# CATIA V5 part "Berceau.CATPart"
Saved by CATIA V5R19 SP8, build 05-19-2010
Part number: Berceau
Publications: "point_axe_pivot_canon_berceau"
Bounding box of the stored display mesh (mm): x -975 to 975, y -1050 to 800, z -150 to 197.999
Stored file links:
  G:\EU_thinkMotion\CFAO_2010\MMS_groupe2\MMS_groupe2\OK\mmartini\mmartiniCFAO\Berceau.CATPart
  C:\Users\Mathieu Martini\Desktop\CFAO\Animation\CFAO.CATProduct
  G:\EU_thinkMotion\CFAO_2010\MMS_groupe2\MMS_groupe2\OK\mmartini\mmartiniCFAO\Squelette.CATPart
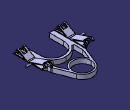
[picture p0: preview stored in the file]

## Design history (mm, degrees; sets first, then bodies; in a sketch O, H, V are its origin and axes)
Parameters
  diametre_canon = 150 mm
External parameters (linked from other documents)
  External.diametre_canon = 150 mm
  External.diametre_verin = 120 mm
AxisSystem1: origin (0, 0, 0), X (1, 0, 0), Y (0, 1, 0), Z (0, 0, 1)
Set1
  Sketch1 on Plane1, origin (0, 0, 0), H (1, 0, 0), V (0, 1, 0)
    circle A1 centre (0, 450) radius 300
    point P1 (0, 450)
    reference projected point E1 (0, 450) from Point2
    arc A2 centre (0, 450) radius 350 from (325.3452, 579.0368) to (-325.3452, 579.0368) ccw
    reference intersected line E2 through (0, 900) direction (-1, 0) from Plane2
    line L1 (555, 0) -> (325.3452, 579.0368)
    point P2 (325.3452, 579.0368)
    point P3 (555, 0)
    reference projected line E3 through (0, 0) direction (1, 0) from Line1
    reference projected point E4 (675, 0) from Point3
    line L2 (555, 0) -> (555, -570)
    point P4 (555, 0)
    point P5 (555, -570)
    reference projected line E5 through (0, -450) direction (1, 0) from Line2
    point P6 (555, -570)
    line L3 (555, -570) -> (405, -570)
    point P7 (405, -570)
    arc A3 centre (0, -570) radius 405 from (405, -570) to (-405, -570) ccw
    point P8 (0, -570)
    reference projected line E6 through (0, 0) direction (0, 1) from Line3
    axis line L4 (0, 455.2396) -> (0, -570)
    point P9 (0, 455.2396)
    point P10 (-555, -570)
    point P11 (-555, 0)
    line L5 (-555, 0) -> (-555, -570)
    point P12 (-405, -570)
    line L6 (-555, -570) -> (-405, -570)
    point P13 (-325.3452, 579.0368)
    point P14 (-555, 0)
    line L7 (-555, 0) -> (-325.3452, 579.0368)
    line L8 (335.4492, 350.131) -> (474.3165, 0)
    point P15 (335.4492, 350.131)
    point P16 (474.3165, 0)
    reference projected line E7 through (0, 0) direction (1, 0) from Line1
    line L9 (474.3165, 0) -> (474.3165, -303.6424)
    line L10 (474.3165, -303.6424) -> (399.3165, -303.6424)
    point P17 (474.3165, -303.6424)
    point P18 (399.3165, -303.6424)
    arc A4 centre (0, -570) radius 480 from (399.3165, -303.6424) to (0, -90) ccw
    point P19 (0, -90)
    point P20 (-474.3165, 0)
    point P21 (-335.4492, 350.131)
    line L11 (-335.4492, 350.131) -> (-474.3165, 0)
    point P22 (-474.3165, -303.6424)
    line L12 (-474.3165, 0) -> (-474.3165, -303.6424)
    point P23 (-399.3165, -303.6424)
    line L13 (-474.3165, -303.6424) -> (-399.3165, -303.6424)
    point P24 (0, -90)
    arc A5 centre (0, -570) radius 480 from (-399.3165, -303.6424) to (0, -90) cw
    arc A6 centre (0, 450) radius 350 from (-335.4492, 350.131) to (335.4492, 350.131) ccw
    radius A1 = 300 {= External.diametre_canon *2}
    distance A2 E2 = 100 {= External.diametre_canon /1.5}
    distance E4 P3 = 120 {= External.diametre_verin}
    distance P5 E5 = 120 {= External.diametre_verin}
    distance P8 L3 = 0
    length L3 = 150 {= External.diametre_canon}
    distance L8 L1 = 75 {= External.diametre_canon /2}
    length L10 = 75 {= External.diametre_canon /2}
    distance A4 A3 = 75 {= External.diametre_canon /2}
    coincidence: P1 E1, P3 E3, P4 H, P6 P5, P8 E6, P9 V, P4 P3, P16 E7, L4 P19, A2 A6, P11 P14, P19 P24
    tangency: L1 A2
    vertical: L2 V, L4 V
    horizontal: L3 H, L10 H
    symmetry: P5 P10 L4, P4 P11 L4, L2 L5 L4, P7 P12 L4, L3 L6 L4, P2 P13 L4, P3 P14 L4, L1 L7 L4, P16 P20 L4, P15 P21 L4, L8 L11 L4, P17 P22 L4, L9 L12 L4, P18 P23 L4, L10 L13 L4, P19 P24 L4, A4 A5 L4
    parallelism: L9 L2
  Point1 "point_axe_pivot_canon_berceau": (0, 450 {= diametre_canon *3}, 0)
Set2
  Plane1: linked copy from another document
  Point2 "point_axe_pivot_canon_berceau": linked copy from another document
  Plane2 "Plan_berceaumax": linked copy from another document
  Line1 "Droite_plan_de_construction_verin": linked copy from another document
  Point3 "Point_verin_droit": linked copy from another document
  Line2 "axe_berceau_jambe_roue": linked copy from another document
  Line3 "axe_canon": linked copy from another document
  Point4 "pt_canonvertical": linked copy from another document
  Plane3 "Plan_rayon_int_verin_droit": linked copy from another document
  Plane4 "arret_berceau_droit": linked copy from another document
  Plane5 "arret_berceau_gauche": linked copy from another document
  Plane6 "arret_berceau_ext_droit": linked copy from another document
  Point5: linked copy from another document
  Plane7 "arret_berceau_ext_gauche": linked copy from another document
  Plane8 "Plan_verin_gauche": linked copy from another document
  Point6: linked copy from another document
  Plane9 "Plan_verin_droit": linked copy from another document
  Plane10: linked copy from another document
  Plane11 "Plan_rayon_ext_verin_droit": linked copy from another document
  Line4 "axe_berceau_jambe": linked copy from another document
  Plane12 "arret_berceau_droit": linked copy from another document
  Plane13 "Plan_rayon_ext_verin_gauche": linked copy from another document
Body1 (main body)
  Pad1: profile Sketch1, direction (0, 0, -1), length 150 {= External.diametre_canon}
  Sketch2 on face of Pad1 from Sketch1.L1, origin (479.563, 190.202, 515.9045), H (0.1359, -0.3427, -0.9296), V (-0.3427, 0.8641, -0.3687)
    circle A1 centre (0, 450) radius 300
    point P1 (0, 450)
    reference projected point E1 (325.3452, 579.0368) from Point2
    arc A2 centre (0, 450) radius 445.2859 from (434.875, 545.7247) to (-434.875, 545.7247) ccw
    reference intersected line E2 through (13.9508, 826.9849) direction (-0.9296, -0.3687) from Plane2
    line L1 (555, 0) -> (434.875, 545.7247)
    point P2 (434.875, 545.7247)
    point P3 (555, 0)
    reference projected line E3 through (486.2175, 715.9045) direction (0.3687, -0.9296) from Line1
    reference projected point E4 (757.2222, 32.6106) from Point3
    line L2 (555, 0) -> (555, -570)
    point P4 (555, 0)
    point P5 (555, -570)
    reference projected line E5 through (463.061, 231.809) direction (0.3687, -0.9296) from Line2
    point P6 (555, -570)
    line L3 (555, -570) -> (405, -570)
    point P7 (405, -570)
    arc A3 centre (0, -570) radius 405 from (405, -570) to (-405, -570) ccw
    point P8 (0, -570)
    reference projected line E6 through (365.9045, 69.9126) direction (-0.3687, 0.9296) from Line3
    axis line L4 (0, 455.2396) -> (0, -570)
    point P9 (0, 455.2396)
    point P10 (-555, -570)
    point P11 (-555, 0)
    line L5 (-555, 0) -> (-555, -570)
    point P12 (-405, -570)
    line L6 (-555, -570) -> (-405, -570)
    point P13 (-434.875, 545.7247)
    point P14 (-555, 0)
    line L7 (-555, 0) -> (-434.875, 545.7247)
    line L8 (414.7961, 288.0627) -> (114.0902, 1654.1622)
    point P15 (414.7961, 288.0627)
    point P16 (114.0902, 1654.1622)
    reference projected line E7 through (486.2175, 715.9045) direction (0.3687, -0.9296) from Line1
    line L9 (114.0902, 1654.1622) -> (114.0902, -91.5944)
    line L10 (114.0902, -91.5944) -> (39.0902, -91.5944)
    point P17 (114.0902, -91.5944)
    point P18 (39.0902, -91.5944)
    arc A4 centre (0, -570) radius 480 from (39.0902, -91.5944) to (0, -90) ccw
    point P19 (0, -90)
    point P20 (-114.0902, 1654.1622)
    point P21 (-414.7961, 288.0627)
    line L11 (-414.7961, 288.0627) -> (-114.0902, 1654.1622)
    point P22 (-114.0902, -91.5944)
    line L12 (-114.0902, 1654.1622) -> (-114.0902, -91.5944)
    point P23 (-39.0902, -91.5944)
    line L13 (-114.0902, -91.5944) -> (-39.0902, -91.5944)
    point P24 (0, -90)
    arc A5 centre (0, -570) radius 480 from (-39.0902, -91.5944) to (0, -90) cw
    arc A6 centre (0, 450) radius 445.2859 from (-414.7961, 288.0627) to (414.7961, 288.0627) ccw
    radius A1 = 300 {= External.diametre_canon *2}
    distance A2 E2 = 100 {= External.diametre_canon /1.5}
    distance E4 P3 = 120 {= External.diametre_verin}
    distance P5 E5 = 120 {= External.diametre_verin}
    distance P8 L3 = 0
    length L3 = 150 {= External.diametre_canon}
    distance L8 L1 = 75 {= External.diametre_canon /2}
    length L10 = 75 {= External.diametre_canon /2}
    distance A4 A3 = 75 {= External.diametre_canon /2}
    coincidence: P1 E1, P3 E3, P4 H, P6 P5, P8 E6, P9 V, P4 P3, P16 E7, L4 P19, A2 A6, P11 P14, P19 P24
    tangency: L1 A2
    vertical: L2 V, L4 V
    horizontal: L3 H, L10 H
    symmetry: P5 P10 L4, P4 P11 L4, L2 L5 L4, P7 P12 L4, L3 L6 L4, P2 P13 L4, P3 P14 L4, L1 L7 L4, P16 P20 L4, P15 P21 L4, L8 L11 L4, P17 P22 L4, L9 L12 L4, P18 P23 L4, L10 L13 L4, P19 P24 L4, A4 A5 L4
    parallelism: L9 L2
  Sketch3 on face of Pad1 from Sketch1.L2, origin (555, 0, 0), H (0, 1, 0), V (0, 0, 1)
    circle A1 centre (0, 150) radius 24
    point P1 (0, 150)
    reference projected point E1 (0, 150) from Point4
    arc A2 centre (0, 150) radius 48 from (-47.1832, 158.8175) to (9.4359, 102.9366) ccw
    point P2 (0, 150)
    line L1 (-15.9554, 195.2706) -> (-570, 0)
    point P4 (-570, 0)
    reference projected point E2 (-570, 0) from vertex [face of Pad1 from Sketch1.L2 | start face of Pad1 | face of Pad1 from Sketch1.L3]
    point P5 (0, 102)
    line L2 (45.476, 134.64) -> (0, 0)
    point P6 (45.476, 134.64)
    line L3 (0, 0) -> (-570, 0)
    point P7 (0, 0)
    line L4 (9.4359, 102.9366) -> (-17.2258, 24)
    line L5 (-17.2258, 24) -> (-429.7032, 24)
    line L6 (-429.7032, 24) -> (-47.1832, 158.8175)
    arc A3 centre (0, 150) radius 48 from (45.476, 134.64) to (-15.9554, 195.2706) ccw
    radius A1 = 24 {= External.diametre_verin /5}
    distance A1 A2 = 24 {= External.diametre_verin /5}
    distance L4 L2 = 24 {= External.diametre_verin /5}
    distance L5 L3 = 24 {= External.diametre_verin /5}
    distance L6 L1 = 24 {= External.diametre_verin /5}
    coincidence: P1 E1, P2 P1, P4 H, P4 E2, P5 A2, P5 V, P6 A2, P7 L2, P7 V, A2 A3, O P7
    tangency: L1 A2, L2 A2
    horizontal: L5 H, L3 H
  Pad2: profile Sketch3, direction (1, 0, 0), up to Plane4
  Sketch4 on face of Pad1 from Sketch1.L5, origin (-555, 0, 0), H (0, -1, 0), V (0, 0, 1)
    projected line E1 (15.9554, 195.2706) -> (570, 0) from edge [start face of Pad2 | face of Pad2 from Sketch3.L1]
    projected line E2 (570, 0) -> (0, 0) from edge [start face of Pad2 | start face of Pad1]
    projected line E3 (0, 0) -> (-45.476, 134.64) from edge [start face of Pad2 | face of Pad2 from Sketch3.L2]
    projected arc E4 centre (0, 150) radius 48 from (15.9554, 195.2706) to (-45.476, 134.64) ccw from edge [start face of Pad2 | face of Pad2 from Sketch3.A3]
    projected circle E5 centre (0, 150) radius 24 from edge [face of Pad2 from Sketch3.A1 | start face of Pad2]
    projected arc E6 centre (0, 150) radius 48 from (-9.4359, 102.9366) to (47.1832, 158.8175) ccw from edge [face of Pad2 from Sketch3.A2 | start face of Pad2]
    projected line E7 (17.2258, 24) -> (-9.4359, 102.9366) from edge [face of Pad2 from Sketch3.L4 | start face of Pad2]
    projected line E8 (429.7032, 24) -> (17.2258, 24) from edge [face of Pad2 from Sketch3.L5 | start face of Pad2]
    projected line E9 (47.1832, 158.8175) -> (429.7032, 24) from edge [face of Pad2 from Sketch3.L6 | start face of Pad2]
  Pad3: profile Sketch4, direction (-1, 0, 0), up to Plane5
  Sketch5 on Plane6, origin (750, 0, 0), H (0, 1, 0), V (0, 0, 1)
    projected arc E1 centre (0, 150) radius 48 from (45.476, 134.64) to (-15.9554, 195.2706) ccw from edge [face of Pad2 from Sketch3.A3 | end face of Pad2]
    projected line E2 (-15.9554, 195.2706) -> (-570, 0) from edge [face of Pad2 from Sketch3.L1 | end face of Pad2]
    projected circle E3 centre (0, 150) radius 24 from edge [end face of Pad2 | face of Pad2 from Sketch3.A1]
    projected line E4 (-429.7032, 24) -> (-47.1832, 158.8175) from edge [face of Pad2 from Sketch3.L6 | end face of Pad2]
    point P6 (-47.1832, 158.8175)
    projected arc E5 centre (0, 150) radius 48 from (-47.1832, 158.8175) to (9.4359, 102.9366) ccw from edge [face of Pad2 from Sketch3.A2 | end face of Pad2]
    projected arc E6 centre (0, 150) radius 48 from (-47.1832, 158.8175) to (-21.9349, 107.305) ccw from edge [face of Pad2 from Sketch3.A2 | end face of Pad2]
    point P7 (-47.1832, 158.8175)
    point P8 (9.4359, 102.9366)
    line L1 (45.476, 134.64) -> (-107.5816, 0)
    point P9 (-107.5816, 0)
    line L2 (-107.5816, 0) -> (-570, 0)
    point P10 (-107.5816, 0)
    line L3 (-429.7032, 24) -> (-116.6354, 24)
    line L4 (-116.6354, 24) -> (-21.9349, 107.305)
    point P12 (-21.9349, 107.305)
    distance L4 L1 = 24 {= External.diametre_verin /5}
    coincidence: L1 P8, P9 H, P10 H, P12 E5, P6 P7, P9 P10
    horizontal: L2 H, L3 H
  Pad4: profile Sketch5, direction (1, 0, 0), length 50 {= External.diametre_canon /3}
  Sketch6 on end face of Pad2, origin (600, 0, 0), H (0, 1, 0), V (0, 0, 1)
    projected line E1 (-15.9554, 195.2706) -> (-570, 0) from edge [face of Pad4 from Sketch5.E2 | end face of Pad4]
    projected line E2 (-107.5816, 162.9773) -> (-570, 0) from edge [face of Pad4 from Sketch5.E2 | end face of Pad4]
    point P2 (-570, 0)
    projected line E3 (-570, 0) -> (-107.5816, 0) from edge [face of Pad4 from Sketch5.L2 | end face of Pad4]
    point P3 (-570, 0)
    point P4 (-107.5816, 0)
    projected line E4 (-47.1832, 158.8175) -> (-429.7032, 24) from edge [end face of Pad4 | face of Pad4 from Sketch5.E4]
    projected line E5 (-107.5816, 137.5303) -> (-429.7032, 24) from edge [end face of Pad4 | face of Pad4 from Sketch5.E4]
    point P7 (-429.7032, 24)
    projected line E6 (-116.6354, 24) -> (-21.9349, 107.305) from edge [end face of Pad4 | face of Pad4 from Sketch5.L4]
    projected line E7 (-429.7032, 24) -> (-116.6354, 24) from edge [end face of Pad4 | face of Pad4 from Sketch5.L3]
    point P10 (-429.7032, 24)
    axis line L1 (-107.5816, -5.232) -> (-107.5816, 242.1501)
    line L2 (-107.5816, 162.9773) -> (-107.5816, 137.5303)
    point P13 (-107.5816, 162.9773)
    point P14 (-107.5816, 137.5303)
    point P15 (-107.5816, 162.9773)
    point P16 (-107.5816, 137.5303)
    line L3 (-107.5816, 0) -> (-116.6354, 24)
    distance P4 L2 = 0
    vertical: L1 V, L2 V
    coincidence: P13 E1, P13 L1, P14 E4, L1 P15, L1 P16, P2 P3, P7 P10, P13 P15, P14 P16
  Pad5: profile Sketch6, direction (1, 0, 0), up to start face of Pad4
  Sketch7 on face of Pad2, origin (0, 0, 0), H (1, 0, 0), V (0, -1, 0)
  Sketch8 on face of Pad1 from Sketch1.L3, origin (0, -570, 0), H (1, 0, 0), V (0, 0, 1)
    projected line E1 (800, 0) -> (555, 0) from edge of Sketch7
    projected line E2 (555, 0) -> (555, -150) from edge [face of Pad1 from Sketch1.L3 | face of Pad1 from Sketch1.L2]
    line L1 (800, 0) -> (555, -150)
  SolidCombine1: FirstComponentProfile Sketch7, FirstComponentDirection Sketch7, SecondComponentProfile Sketch8, SecondComponentDirection Sketch8
  Sketch9 on Plane7, origin (-750, 0, 0), H (0, 1, 0), V (0, 0, 1)
    projected arc E1 centre (0, 150) radius 48 from (45.476, 134.64) to (-15.9554, 195.2706) ccw from edge [face of Pad4 from Sketch5.E1 | end face of Pad4]
    projected line E2 (-15.9554, 195.2706) -> (-570, 0) from edge [face of Pad2 | end face of Pad4]
    projected line E3 (-107.5816, 0) -> (-570, 0) from edge [end face of Pad4 | face of SolidCombine1 from Sketch8.L1]
    projected line E4 (-107.5816, 0) -> (45.476, 134.64) from edge [face of Pad4 from Sketch5.L1 | end face of Pad4]
    projected circle E5 centre (0, 150) radius 24 from edge [end face of Pad4 | face of Pad4 from Sketch5.E3]
    projected line E6 (-47.1832, 158.8175) -> (-429.7032, 24) from edge [end face of Pad4 | face of Pad2]
    projected arc E7 centre (0, 150) radius 48 from (-47.1832, 158.8175) to (-21.9349, 107.305) ccw from edge [end face of Pad4 | face of Pad4 from Sketch5.E6]
    projected line E8 (-116.6354, 24) -> (-21.9349, 107.305) from edge [end face of Pad4 | face of Pad4 from Sketch5.L4]
    projected line E9 (-429.7032, 24) -> (-116.6354, 24) from edge [end face of Pad4 | face of Pad2]
  Pad6: profile Sketch9, direction (1, 0, 0), length -50 {= -External.diametre_canon /3}
  Sketch10 on end face of Pad3, origin (-600, 0, 0), H (0, -1, 0), V (0, 0, 1)
    projected line E1 (15.9554, 195.2706) -> (570, 0) from edge [end face of Pad6 | face of Pad6 from Sketch9.E2]
    projected line E2 (107.5816, 162.9773) -> (570, 0) from edge [end face of Pad6 | face of Pad6 from Sketch9.E2]
    projected line E3 (570, 0) -> (107.5816, 0) from edge [end face of Pad6 | face of Pad6 from Sketch9.E3]
    point P4 (107.5816, 0)
    projected line E4 (429.7032, 24) -> (116.6354, 24) from edge [face of Pad6 from Sketch9.E9 | end face of Pad6]
    projected line E5 (47.1832, 158.8175) -> (429.7032, 24) from edge [face of Pad6 from Sketch9.E6 | end face of Pad6]
    projected line E6 (107.5816, 137.5303) -> (429.7032, 24) from edge [face of Pad6 from Sketch9.E6 | end face of Pad6]
    line L1 (116.6354, 24) -> (107.5816, 0)
    point P9 (116.6354, 24)
    point P10 (107.5816, 0)
    line L2 (107.5816, 137.5303) -> (107.5816, 162.9773)
    point P11 (107.5816, 137.5303)
    point P12 (107.5816, 162.9773)
    distance L2 P4 = 0
    angle L2 L1 = 159.3315
    coincidence: P9 E4, P10 H, L1 P4, P11 E5, P12 E1, P4 P10
    vertical: L2 V
  Pad7: profile Sketch10, direction (-1, 0, 0), up to start face of Pad6
  Sketch11 on face of Pad3, origin (0, 0, 0), H (1, 0, 0), V (0, -1, 0)
  Sketch12 on face of Pad1 from Sketch1.L6, origin (0, -570, 0), H (1, 0, 0), V (0, 0, 1)
    projected line E1 (-555, 0) -> (-800, 0) from edge of Sketch11
    projected line E2 (-555, 0) -> (-555, -150) from edge [face of Pad1 from Sketch1.L5 | face of Pad1 from Sketch1.L6]
    line L1 (-555, -150) -> (-800, 0)
  SolidCombine2: FirstComponentProfile Sketch11, FirstComponentDirection Sketch11, SecondComponentProfile Sketch12, SecondComponentDirection Sketch12
  Sketch13 on Plane8, origin (-675, 0, 0), H (0, 1, 0), V (0, 0, 1)
    projected line E1 (-570, -150) -> (-570, 0) from edge of Sketch14
    point P1 (-570, -150)
    line L1 (-570, 0) -> (-1050, 0)
    line L2 (-1050, 0) -> (-1050, -150)
    line L3 (-570, -150) -> (-1050, -150)
    point P5 (-570, -150)
    reference projected point E2 (-900, 150) from Point6
    distance L2 E2 = 150 {= External.diametre_canon}
    horizontal: L1 H, L3 H
    vertical: L2 V
    coincidence: P5 E1, P5 P1
  Sketch14 on face of Pad1, origin (0, -570, 0), H (1, 0, 0), V (0, 0, 1)
  SolidCombine3: FirstComponentProfile Sketch13, FirstComponentDirection Sketch13, SecondComponentProfile Sketch14, SecondComponentDirection Sketch14
  Sketch15 on Plane8, origin (-675, 0, 0), H (0, 1, 0), V (0, 0, 1)
    projected point E1 (-1050, 0) from edge of Sketch16
    point P1 (-1050, 0)
    line L1 (-1050, 0) -> (-933.1102, 172.4436)
    point P3 (-900, 150)
    reference projected point E2 (-900, 150) from Point6
    arc A1 centre (-900, 150) radius 40 from (-879.5307, 184.3658) to (-933.1102, 172.4436) ccw
    line L2 (-570, 0) -> (-879.5307, 184.3658)
    line L3 (-1050, 0) -> (-570, 0)
    radius A1 = 40 {= External.diametre_verin /3}
    coincidence: P1 E1, P3 E2
    tangency: L2 A1, L1 A1
    horizontal: L3 H
  Sketch16 on face of SolidCombine3, origin (0, 0, 0), H (1, 0, 0), V (0, 1, 0)
  SolidCombine4: FirstComponentProfile Sketch15, FirstComponentDirection Sketch15, SecondComponentProfile Sketch16, SecondComponentDirection Sketch16
  Sketch17 on face of Pad1, origin (0, -570, 0), H (1, 0, 0), V (0, 0, 1)
  Sketch18 on Plane9, origin (675, 0, 0), H (0, 1, 0), V (0, 0, 1)
  SolidCombine5: FirstComponentProfile Sketch17, FirstComponentDirection Sketch17, SecondComponentProfile Sketch18, SecondComponentDirection Sketch18
  Sketch19 on Plane9, origin (675, 0, 0), H (0, 1, 0), V (0, 0, 1)
  Sketch20 on face of Pad1, origin (0, 0, 0), H (1, 0, 0), V (0, 1, 0)
    projected line E1 (555, -570) -> (800, -570) from edge [face of Pad1 | face of Pad2]
    projected line E2 (800, -570) -> (800, -1050) from edge [face of Pad1 | face of SolidCombine1]
    point P4 (800, -1050)
    projected line E3 (405, -1050) -> (800, -1050) from edge [face of SolidCombine5 | face of Pad1]
    projected line E4 (555, -1050) -> (800, -1050) from edge [face of SolidCombine5 | face of Pad1]
    point P6 (800, -1050)
    line L1 (555, -570) -> (555, -1050)
    point P7 (555, -1050)
    coincidence: P7 E3, P4 P6
    vertical: L1 V
  SolidCombine6: FirstComponentProfile Sketch19, FirstComponentDirection Sketch19, SecondComponentProfile Sketch20, SecondComponentDirection Sketch20
  Sketch21 on Plane10, origin (0, 0, 0), H (0, 1, 0), V (0, 0, 1)
    circle A1 centre (-900, 150) radius 24
    point P1 (-900, 150)
    reference projected point E1 (-900, 150) from Point6
    radius A1 = 24 {= External.diametre_verin /5}
    coincidence: P1 E1
  Pocket1: profile Sketch21, direction (-1, 0, 0), up to face of SolidCombine6 from Sketch20.E2, opposite side up to face of SolidCombine4
  Fillet1: radius 50 {= External.diametre_canon /3}, on edge [face of SolidCombine4 from Sketch15.L2 | face of Pad3]
  Fillet2: radius 50 {= External.diametre_canon /3}, on edge [face of SolidCombine6 | face of Pad2]
  Sketch22 on Plane10, origin (0, 0, 0), H (0, 1, 0), V (0, 0, 1)
    reference projected line E1 (-590.1199, 11.984) -> (-879.5307, 184.3658) from edge [face of SolidCombine6 | face of SolidCombine6]
    reference projected line E2 (-1050, 0) -> (-933.1102, 172.4436) from edge [face of SolidCombine6 | face of SolidCombine6]
    reference projected line E3 (-107.5816, 0) -> (-1050, 0) from edge [face of SolidCombine6 | face of SolidCombine1]
    line L1 (-1002.8518, 25) -> (-933.2221, 127.7223)
    line L2 (-1002.8518, 25) -> (-660.826, 25)
    point P9 (-660.826, 25)
    arc A1 centre (-900, 150) radius 40 from (-933.2221, 127.7223) to (-860.4661, 143.9116) ccw
    point P10 (-900, 150)
    reference projected point E4 (-900, 150) from Point6
    line L3 (-860.4661, 143.9116) -> (-660.826, 25)
    point P12 (-660.826, 25)
    distance L1 E2 = 25 {= External.diametre_canon /6}
    distance L2 E3 = 25 {= External.diametre_canon /6}
    radius A1 = 40 {= External.diametre_verin /3}
    distance L3 E1 = 25 {= External.diametre_canon /6}
    horizontal: L2 H
    coincidence: P10 E4, P12 P9
  Pocket2: profile Sketch22, direction (-1, 0, 0), up to face of SolidCombine4, opposite side up to face of SolidCombine6
  Sketch23 on face of Pocket2 from Sketch22.L2, origin (0, 0, 25), H (1, 0, 0), V (0, 1, 0)
    projected line E1 (555, -1050) -> (800, -1050) from edge [face of SolidCombine5 | face of SolidCombine6]
    projected line E2 (615, -1050) -> (750, -1050) from edge [face of SolidCombine5 | face of SolidCombine6]
    line L1 (750, -1050) -> (750, -750)
    point P3 (750, -1050)
    line L2 (615, -1050) -> (615, -750)
    point P5 (615, -1050)
    line L3 (615, -750) -> (750, -750)
    reference projected line E3 through (0, -900) direction (1, 0) from Line4
    projected line E4 (-800, -1050) -> (-555, -1050) from edge [face of SolidCombine3 from Sketch13.L2 | face of SolidCombine4 from Sketch15.L1]
    projected line E5 (-750, -1050) -> (-600, -1050) from edge [face of SolidCombine3 from Sketch13.L2 | face of SolidCombine4 from Sketch15.L1]
    line L4 (-600, -1050) -> (-600, -780)
    point P9 (-600, -1050)
    line L5 (-750, -1050) -> (-750, -780)
    point P11 (-750, -1050)
    line L6 (-750, -780) -> (-600, -780)
    reference intersected line E6 through (-750, 0) direction (0, 1) from Plane7
    reference intersected line E7 through (-600, 0) direction (0, 1) from Plane5
    reference projected line E8 through (0, -900) direction (1, 0) from Line4
    reference intersected line E9 through (750, 0) direction (0, 1) from Plane6
    reference intersected line E10 through (615, 0) direction (0, 1) from Plane3
    distance L3 E3 = 150 {= External.diametre_canon}
    distance L6 E8 = 120 {= External.diametre_verin}
    coincidence: P3 E1, P5 E1, P9 E4, P11 E4, L5 E6, L4 E7, L1 E9, L2 E10
    vertical: L1 V, L2 V, L4 V, L5 V
    horizontal: L3 H, L6 H
  Pocket3: profile Sketch23, direction (0, 0, 1), through (limit type 3), opposite side through (limit type 3)
  Sketch24 on Plane9, origin (675, 0, 0), H (0, 1, 0), V (0, 0, 1)
    circle A1 centre (-450, 0) radius 24
    point P1 (-450, 0)
    reference projected point E1 (-450, 0) from Point5
    radius A1 = 24 {= External.diametre_verin /5}
    coincidence: P1 E1
  Pad8: profile Sketch24, direction (1, 0, 0), length 300 {= External.diametre_canon *2}
  Sketch25 on Plane8, origin (-675, 0, 0), H (0, 1, 0), V (0, 0, 1)
    circle A1 centre (-450, 0) radius 24
    point P1 (-450, 0)
    reference projected point E1 (-450, 0) from Line2
    radius A1 = 24 {= External.diametre_verin /5}
    coincidence: P1 E1
  Pad9: profile Sketch25, direction (1, 0, 0), length -300 {= -External.diametre_canon *2}
  Pad10: profile Sketch2, direction (-0.9296, -0.3687, 0), length 150 {= External.diametre_canon}, deactivated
